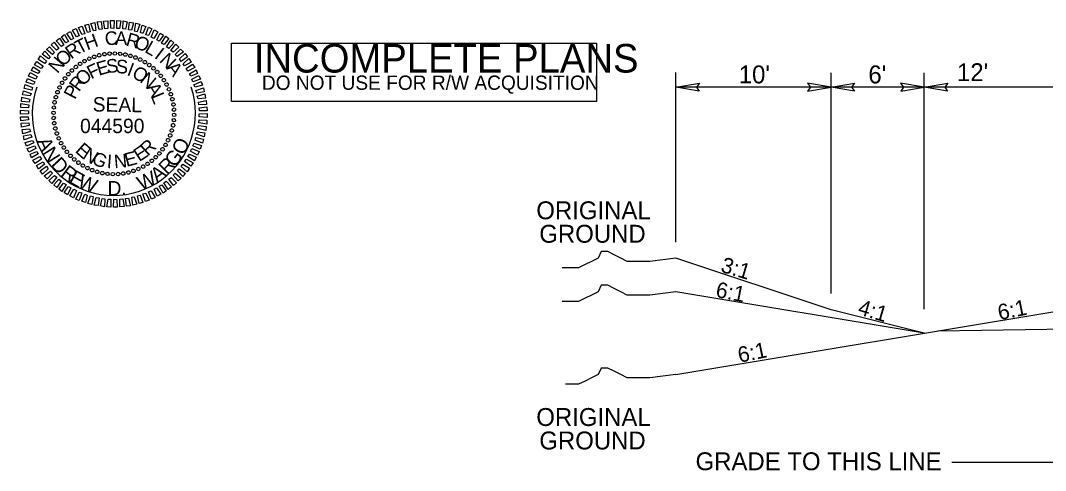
# Model space of a CAD drawing. Extents: x 2176156 to 2177167, y 76401 to 76644.
# Drawn here: x 2176901.7 to 2176967.8, y 76590.1 to 76619.1 of the extents above; entities that cross this region are included whole.
import ezdxf

# ---------------------------------------------------------------- set-up
doc = ezdxf.new("R2010")
doc.units = 0
for name, color, linetype in [('Exist Building', 7, 'Continuous'), ('Exist Roads Curbs', 7, 'Continuous'), ('Exist Roads EOP Other', 7, 'Continuous'), ('Exist Roads Soil', 7, 'Continuous'), ('Exist Structure Minor Culvert Topo', 7, 'Continuous'), ('Old_Level_1', 7, 'Continuous'), ('Old_Level_3', 7, 'Continuous'), ('PH Exist DTM Obscure Area', 7, 'Continuous'), ('Sheet Border Standard 30in CELL', 7, 'Continuous'), ('Sheet Cutting Line CELL', 7, 'Continuous')]:
    doc.layers.add(name, color=color, linetype=linetype)

msp = doc.modelspace()

# ---------------------------------------------------------------- linework, layer by layer
at = {"layer": 'Exist Building'}
msp.add_line((2176960.844, 76599.085), (2176981.96, 76599.4), dxfattribs=at)
at = {"layer": 'Exist Roads Curbs'}
for points in [[(2176943.96, 76603.771), (2176942.289, 76603.563), (2176941.871, 76603.563), (2176941.244, 76603.563), (2176940.826, 76603.563), (2176940.409, 76603.771), (2176939.991, 76603.981), (2176939.573, 76604.191), (2176939.156, 76604.191), (2176938.946, 76603.771), (2176938.528, 76603.563), (2176938.111, 76603.354), (2176937.693, 76603.146), (2176937.275, 76603.146), (2176936.858, 76603.146), (2176936.626, 76603.146)], [(2176943.959, 76601.605), (2176942.289, 76601.397), (2176941.871, 76601.397), (2176941.244, 76601.397), (2176940.826, 76601.397), (2176940.408, 76601.605), (2176939.991, 76601.814), (2176939.573, 76602.024), (2176939.155, 76602.024), (2176938.946, 76601.605), (2176938.528, 76601.397), (2176938.11, 76601.187), (2176937.693, 76600.979), (2176937.275, 76600.979), (2176936.858, 76600.979), (2176936.626, 76600.979)], [(2176943.96, 76596.271), (2176942.289, 76596.063), (2176941.871, 76596.063), (2176941.244, 76596.063), (2176940.826, 76596.063), (2176940.409, 76596.271), (2176939.991, 76596.481), (2176939.573, 76596.691), (2176939.156, 76596.691), (2176938.946, 76596.271), (2176938.528, 76596.063), (2176938.111, 76595.854), (2176937.693, 76595.646), (2176937.275, 76595.646), (2176936.858, 76595.646), (2176936.847, 76595.646)]]:
    msp.add_lwpolyline(points, dxfattribs=at)
at = {"layer": 'Exist Roads EOP Other'}
for p, q in [((2176953.96, 76600.438), (2176943.96, 76603.771)), ((2176959.96, 76598.938), (2176953.96, 76600.438))]:
    msp.add_line(p, q, dxfattribs=at)
at = {"layer": 'Exist Roads Soil'}
for p, q in [((2176959.96, 76598.938), (2176943.96, 76601.605)), ((2176943.96, 76596.271), (2176971.912, 76600.93))]:
    msp.add_line(p, q, dxfattribs=at)
at = {"layer": 'Old_Level_1'}
for points in [[(2176945.469, 76614.521), (2176943.96, 76614.781), (2176945.478, 76615.049), (2176945.285, 76614.781)], [(2176952.45, 76614.521), (2176953.96, 76614.781), (2176952.442, 76615.049), (2176952.635, 76614.781)], [(2176955.469, 76614.521), (2176953.96, 76614.781), (2176955.478, 76615.049), (2176955.285, 76614.781)], [(2176958.45, 76614.521), (2176959.96, 76614.781), (2176958.442, 76615.049), (2176958.635, 76614.781)], [(2176961.469, 76614.521), (2176959.96, 76614.781), (2176961.478, 76615.049), (2176961.285, 76614.781)]]:
    msp.add_lwpolyline(points, close=True, dxfattribs=at)
at = {"layer": 'Old_Level_3'}
for p, q in [((2176943.96, 76604.802), (2176943.96, 76615.735)), ((2176953.96, 76601.501), (2176953.96, 76615.709)), ((2176959.96, 76600.483), (2176959.96, 76615.709)), ((2176953.96, 76614.781), (2176943.96, 76614.781)), ((2176959.96, 76614.781), (2176953.96, 76614.781)), ((2176971.96, 76614.781), (2176959.96, 76614.781)), ((2176961.746, 76590.631), (2176971.314, 76590.631))]:
    msp.add_line(p, q, dxfattribs=at)
at = {"layer": 'PH Exist DTM Obscure Area'}
for p, q in [((2176905.86, 76616.472), (2176905.86, 76616.472)), ((2176906.162, 76616.627), (2176906.162, 76616.627)), ((2176906.472, 76616.751), (2176906.472, 76616.751)), ((2176906.798, 76616.844), (2176906.798, 76616.844)), ((2176907.139, 76616.906), (2176907.139, 76616.906)), ((2176907.472, 76616.953), (2176907.472, 76616.953)), ((2176907.813, 76616.96), (2176907.813, 76616.96)), ((2176908.154, 76616.937), (2176908.154, 76616.937)), ((2176908.487, 76616.883), (2176908.487, 76616.883)), ((2176908.813, 76616.813), (2176908.813, 76616.813)), ((2176909.138, 76616.705), (2176909.138, 76616.705)), ((2176909.448, 76616.565), (2176909.448, 76616.565)), ((2176905.039, 76615.868), (2176905.039, 76615.868)), ((2176905.294, 76616.1), (2176905.294, 76616.1)), ((2176905.566, 76616.294), (2176905.566, 76616.294)), ((2176909.751, 76616.41), (2176909.751, 76616.41)), ((2176910.03, 76616.216), (2176910.03, 76616.216)), ((2176910.301, 76616.007), (2176910.301, 76616.007)), ((2176910.541, 76615.775), (2176910.541, 76615.775)), ((2176904.597, 76615.356), (2176904.597, 76615.356)), ((2176904.806, 76615.627), (2176904.806, 76615.627)), ((2176910.774, 76615.519), (2176910.774, 76615.519)), ((2176910.967, 76615.248), (2176910.967, 76615.248)), ((2176904.109, 76614.465), (2176904.109, 76614.465)), ((2176904.248, 76614.775), (2176904.248, 76614.775)), ((2176904.403, 76615.077), (2176904.403, 76615.077)), ((2176911.146, 76614.953), (2176911.146, 76614.953)), ((2176911.301, 76614.651), (2176911.301, 76614.651)), ((2176903.93, 76613.814), (2176903.93, 76613.814)), ((2176904, 76614.139), (2176904, 76614.139)), ((2176911.425, 76614.341), (2176911.425, 76614.341)), ((2176911.518, 76614.015), (2176911.518, 76614.015)), ((2176903.853, 76613.14), (2176903.853, 76613.14)), ((2176903.876, 76613.481), (2176903.876, 76613.481)), ((2176911.58, 76613.674), (2176911.58, 76613.674)), ((2176911.626, 76613.341), (2176911.626, 76613.341)), ((2176903.861, 76612.799), (2176903.861, 76612.799)), ((2176903.907, 76612.465), (2176903.907, 76612.465)), ((2176911.611, 76612.659), (2176911.611, 76612.659)), ((2176911.634, 76613), (2176911.634, 76613)), ((2176903.969, 76612.124), (2176903.969, 76612.124)), ((2176904.062, 76611.799), (2176904.062, 76611.799)), ((2176911.487, 76612), (2176911.487, 76612)), ((2176911.556, 76612.326), (2176911.556, 76612.326)), ((2176904.186, 76611.489), (2176904.186, 76611.489)), ((2176904.341, 76611.187), (2176904.341, 76611.187)), ((2176911.239, 76611.365), (2176911.239, 76611.365)), ((2176911.378, 76611.675), (2176911.378, 76611.675)), ((2176904.519, 76610.892), (2176904.519, 76610.892)), ((2176904.713, 76610.621), (2176904.713, 76610.621)), ((2176910.681, 76610.512), (2176910.681, 76610.512)), ((2176910.89, 76610.784), (2176910.89, 76610.784)), ((2176911.084, 76611.063), (2176911.084, 76611.063)), ((2176904.946, 76610.365), (2176904.946, 76610.365)), ((2176905.186, 76610.133), (2176905.186, 76610.133)), ((2176905.457, 76609.923), (2176905.457, 76609.923)), ((2176909.921, 76609.846), (2176909.921, 76609.846)), ((2176910.192, 76610.04), (2176910.192, 76610.04)), ((2176910.448, 76610.272), (2176910.448, 76610.272)), ((2176905.736, 76609.73), (2176905.736, 76609.73)), ((2176906.038, 76609.575), (2176906.038, 76609.575)), ((2176906.348, 76609.435), (2176906.348, 76609.435)), ((2176906.674, 76609.327), (2176906.674, 76609.327)), ((2176906.999, 76609.257), (2176906.999, 76609.257)), ((2176907.333, 76609.203), (2176907.333, 76609.203)), ((2176907.674, 76609.179), (2176907.674, 76609.179)), ((2176908.015, 76609.187), (2176908.015, 76609.187)), ((2176908.348, 76609.234), (2176908.348, 76609.234)), ((2176908.689, 76609.296), (2176908.689, 76609.296)), ((2176909.014, 76609.389), (2176909.014, 76609.389)), ((2176909.324, 76609.513), (2176909.324, 76609.513)), ((2176909.627, 76609.668), (2176909.627, 76609.668))]:
    msp.add_line(p, q, dxfattribs=at)
for points in [[(2176907.17, 76618.541), (2176907.085, 76619.037), (2176907.348, 76619.068), (2176907.356, 76618.565)], [(2176907.557, 76618.58), (2176907.519, 76619.084), (2176907.774, 76619.076), (2176907.743, 76618.572)], [(2176907.929, 76618.572), (2176907.929, 76619.076), (2176908.185, 76619.068), (2176908.115, 76618.565)], [(2176905.333, 76618.022), (2176905.085, 76618.456), (2176905.325, 76618.565), (2176905.504, 76618.092)], [(2176905.674, 76618.185), (2176905.473, 76618.634), (2176905.705, 76618.727), (2176905.868, 76618.231)], [(2176906.054, 76618.309), (2176905.876, 76618.774), (2176906.116, 76618.844), (2176906.217, 76618.363)], [(2176906.426, 76618.41), (2176906.263, 76618.898), (2176906.527, 76618.952), (2176906.589, 76618.448)], [(2176906.798, 76618.495), (2176906.674, 76618.991), (2176906.93, 76619.014), (2176906.984, 76618.518)], [(2176908.317, 76618.549), (2176908.348, 76619.053), (2176908.604, 76619.006), (2176908.503, 76618.518)], [(2176908.689, 76618.487), (2176908.759, 76618.983), (2176909.014, 76618.944), (2176908.875, 76618.464)], [(2176909.084, 76618.402), (2176909.162, 76618.906), (2176909.425, 76618.844), (2176909.247, 76618.363)], [(2176909.456, 76618.301), (2176909.572, 76618.782), (2176909.813, 76618.704), (2176909.619, 76618.247)], [(2176909.805, 76618.162), (2176909.983, 76618.65), (2176910.2, 76618.557), (2176909.983, 76618.107)], [(2176910.154, 76618.014), (2176910.347, 76618.472), (2176910.588, 76618.363), (2176910.324, 76617.929)], [(2176904.364, 76617.41), (2176904.031, 76617.782), (2176904.24, 76617.945), (2176904.512, 76617.511)], [(2176904.659, 76617.642), (2176904.372, 76618.038), (2176904.574, 76618.185), (2176904.829, 76617.735)], [(2176905, 76617.836), (2176904.713, 76618.255), (2176904.953, 76618.379), (2176905.147, 76617.929)], [(2176910.51, 76617.836), (2176910.719, 76618.278), (2176910.952, 76618.146), (2176910.657, 76617.743)], [(2176910.812, 76617.627), (2176911.084, 76618.076), (2176911.285, 76617.914), (2176910.983, 76617.534)], [(2176911.13, 76617.394), (2176911.417, 76617.821), (2176911.618, 76617.65), (2176911.277, 76617.286)], [(2176903.527, 76616.604), (2176903.124, 76616.906), (2176903.295, 76617.108), (2176903.636, 76616.743)], [(2176903.799, 76616.898), (2176903.403, 76617.216), (2176903.597, 76617.394), (2176903.923, 76617.022)], [(2176904.054, 76617.17), (2176903.713, 76617.511), (2176903.899, 76617.697), (2176904.202, 76617.278)], [(2176911.425, 76617.154), (2176911.742, 76617.557), (2176911.928, 76617.371), (2176911.572, 76617.038)], [(2176911.704, 76616.883), (2176912.037, 76617.247), (2176912.223, 76617.061), (2176911.82, 76616.759)], [(2176903.062, 76615.999), (2176902.628, 76616.232), (2176902.783, 76616.449), (2176903.186, 76616.139)], [(2176903.295, 76616.309), (2176902.876, 76616.573), (2176903.024, 76616.798), (2176903.396, 76616.457)], [(2176911.975, 76616.604), (2176912.331, 76616.953), (2176912.494, 76616.743), (2176912.083, 76616.449)], [(2176912.207, 76616.302), (2176912.587, 76616.627), (2176912.734, 76616.402), (2176912.3, 76616.154)], [(2176902.876, 76615.666), (2176902.435, 76615.86), (2176902.551, 76616.1), (2176902.969, 76615.813)], [(2176912.409, 76615.984), (2176912.82, 76616.278), (2176912.967, 76616.046), (2176912.517, 76615.829)], [(2176912.61, 76615.643), (2176913.044, 76615.914), (2176913.145, 76615.674), (2176912.703, 76615.496)], [(2176902.566, 76614.969), (2176902.086, 76615.108), (2176902.187, 76615.348), (2176902.652, 76615.131)], [(2176902.721, 76615.31), (2176902.241, 76615.488), (2176902.357, 76615.728), (2176902.799, 76615.48)], [(2176912.765, 76615.31), (2176913.223, 76615.542), (2176913.323, 76615.294), (2176912.843, 76615.139)], [(2176912.905, 76614.945), (2176913.378, 76615.147), (2176913.463, 76614.907), (2176912.982, 76614.783)], [(2176902.349, 76614.225), (2176901.869, 76614.287), (2176901.923, 76614.55), (2176902.411, 76614.387)], [(2176902.45, 76614.597), (2176901.97, 76614.697), (2176902.024, 76614.953), (2176902.512, 76614.759)], [(2176913.029, 76614.573), (2176913.525, 76614.752), (2176913.571, 76614.496), (2176913.083, 76614.411)], [(2176902.287, 76613.829), (2176901.791, 76613.876), (2176901.822, 76614.139), (2176902.326, 76614.015)], [(2176913.122, 76614.201), (2176913.61, 76614.349), (2176913.657, 76614.085), (2176913.168, 76614.039)], [(2176913.192, 76613.829), (2176913.695, 76613.938), (2176913.719, 76613.674), (2176913.223, 76613.643)], [(2176902.241, 76613.07), (2176901.737, 76613.047), (2176901.737, 76613.31), (2176902.241, 76613.256)], [(2176902.249, 76613.457), (2176901.745, 76613.473), (2176901.76, 76613.729), (2176902.264, 76613.643)], [(2176913.238, 76613.457), (2176913.742, 76613.519), (2176913.757, 76613.256), (2176913.254, 76613.271)], [(2176902.249, 76612.682), (2176901.745, 76612.62), (2176901.729, 76612.884), (2176902.233, 76612.868)], [(2176902.295, 76612.31), (2176901.791, 76612.202), (2176901.768, 76612.465), (2176902.264, 76612.496)], [(2176913.238, 76612.682), (2176913.742, 76612.667), (2176913.726, 76612.411), (2176913.223, 76612.496)], [(2176913.246, 76613.07), (2176913.75, 76613.093), (2176913.75, 76612.83), (2176913.246, 76612.884)], [(2176902.365, 76611.938), (2176901.877, 76611.791), (2176901.83, 76612.055), (2176902.318, 76612.101)], [(2176913.137, 76611.915), (2176913.618, 76611.853), (2176913.564, 76611.59), (2176913.075, 76611.752)], [(2176913.199, 76612.31), (2176913.695, 76612.264), (2176913.664, 76612), (2176913.161, 76612.124)], [(2176902.458, 76611.566), (2176901.962, 76611.388), (2176901.915, 76611.644), (2176902.404, 76611.729)], [(2176902.582, 76611.194), (2176902.109, 76610.993), (2176902.024, 76611.233), (2176902.504, 76611.357)], [(2176912.92, 76611.171), (2176913.401, 76611.032), (2176913.3, 76610.791), (2176912.835, 76611.008)], [(2176913.037, 76611.543), (2176913.517, 76611.442), (2176913.463, 76611.187), (2176912.975, 76611.38)], [(2176902.721, 76610.83), (2176902.264, 76610.598), (2176902.163, 76610.846), (2176902.644, 76611.001)], [(2176902.876, 76610.497), (2176902.442, 76610.226), (2176902.342, 76610.466), (2176902.783, 76610.644)], [(2176912.61, 76610.474), (2176913.052, 76610.28), (2176912.936, 76610.04), (2176912.517, 76610.326)], [(2176912.765, 76610.83), (2176913.246, 76610.652), (2176913.13, 76610.412), (2176912.688, 76610.66)], [(2176903.078, 76610.156), (2176902.667, 76609.861), (2176902.52, 76610.094), (2176902.969, 76610.311)], [(2176903.279, 76609.838), (2176902.9, 76609.513), (2176902.752, 76609.737), (2176903.186, 76609.985)], [(2176912.192, 76609.83), (2176912.61, 76609.567), (2176912.463, 76609.342), (2176912.091, 76609.683)], [(2176912.424, 76610.14), (2176912.858, 76609.908), (2176912.703, 76609.691), (2176912.3, 76610.001)], [(2176903.512, 76609.536), (2176903.155, 76609.187), (2176902.993, 76609.396), (2176903.403, 76609.691)], [(2176903.783, 76609.257), (2176903.45, 76608.893), (2176903.264, 76609.079), (2176903.667, 76609.381)], [(2176911.688, 76609.241), (2176912.083, 76608.924), (2176911.89, 76608.745), (2176911.564, 76609.117)], [(2176911.959, 76609.536), (2176912.362, 76609.234), (2176912.192, 76609.032), (2176911.851, 76609.396)], [(2176904.062, 76608.986), (2176903.744, 76608.583), (2176903.558, 76608.769), (2176903.915, 76609.102)], [(2176904.357, 76608.745), (2176904.07, 76608.319), (2176903.868, 76608.49), (2176904.209, 76608.854)], [(2176904.674, 76608.513), (2176904.403, 76608.063), (2176904.202, 76608.226), (2176904.504, 76608.606)], [(2176910.828, 76608.497), (2176911.115, 76608.102), (2176910.913, 76607.955), (2176910.657, 76608.404)], [(2176911.122, 76608.73), (2176911.456, 76608.358), (2176911.246, 76608.195), (2176910.975, 76608.629)], [(2176911.432, 76608.97), (2176911.773, 76608.629), (2176911.587, 76608.443), (2176911.285, 76608.862)], [(2176904.977, 76608.304), (2176904.767, 76607.862), (2176904.535, 76607.994), (2176904.829, 76608.397)], [(2176905.333, 76608.125), (2176905.139, 76607.668), (2176904.899, 76607.777), (2176905.163, 76608.211)], [(2176905.682, 76607.978), (2176905.504, 76607.49), (2176905.287, 76607.583), (2176905.504, 76608.032)], [(2176906.031, 76607.839), (2176905.914, 76607.358), (2176905.674, 76607.436), (2176905.868, 76607.893)], [(2176909.433, 76607.831), (2176909.611, 76607.366), (2176909.371, 76607.296), (2176909.27, 76607.777)], [(2176909.813, 76607.955), (2176910.014, 76607.505), (2176909.782, 76607.412), (2176909.619, 76607.908)], [(2176910.154, 76608.118), (2176910.402, 76607.684), (2176910.161, 76607.575), (2176909.983, 76608.048)], [(2176910.487, 76608.304), (2176910.774, 76607.885), (2176910.533, 76607.761), (2176910.34, 76608.211)], [(2176906.403, 76607.738), (2176906.325, 76607.234), (2176906.062, 76607.296), (2176906.24, 76607.777)], [(2176906.798, 76607.653), (2176906.728, 76607.157), (2176906.472, 76607.195), (2176906.612, 76607.676)], [(2176907.17, 76607.591), (2176907.139, 76607.087), (2176906.883, 76607.133), (2176906.984, 76607.622)], [(2176907.557, 76607.567), (2176907.557, 76607.064), (2176907.302, 76607.071), (2176907.371, 76607.575)], [(2176907.929, 76607.56), (2176907.968, 76607.056), (2176907.712, 76607.064), (2176907.743, 76607.567)], [(2176908.317, 76607.598), (2176908.402, 76607.102), (2176908.139, 76607.071), (2176908.131, 76607.575)], [(2176908.689, 76607.645), (2176908.813, 76607.149), (2176908.557, 76607.126), (2176908.503, 76607.622)], [(2176909.061, 76607.73), (2176909.224, 76607.242), (2176908.96, 76607.188), (2176908.898, 76607.691)]]:
    msp.add_lwpolyline(points, close=True, dxfattribs=at)
for centre, major_axis in [((2176905.57, 76616.293), (-0.0624, 0.0925)), ((2176905.859, 76616.47), (-0.0541, 0.0976)), ((2176906.162, 76616.621), (-0.045, 0.102)), ((2176906.478, 76616.745), (-0.036, 0.106)), ((2176906.803, 76616.842), (-0.027, 0.108)), ((2176907.135, 76616.909), (-0.017, 0.11)), ((2176907.472, 76616.948), (-0.008, 0.111)), ((2176907.811, 76616.957), (0.002, 0.112)), ((2176908.15, 76616.936), (0.012, 0.111)), ((2176908.485, 76616.886), (0.021, 0.11)), ((2176908.815, 76616.807), (0.031, 0.107)), ((2176909.137, 76616.699), (0.04, 0.104)), ((2176909.448, 76616.564), (0.049, 0.1)), ((2176909.746, 76616.402), (0.0575, 0.0957)), ((2176905.043, 76615.866), (-0.0775, 0.0803)), ((2176905.297, 76616.091), (-0.0702, 0.0867)), ((2176910.028, 76616.215), (0.0656, 0.0903)), ((2176910.294, 76616.004), (0.0732, 0.0842)), ((2176910.54, 76615.77), (0.0803, 0.0775)), ((2176904.411, 76615.072), (-0.0957, 0.0575)), ((2176904.598, 76615.355), (-0.0903, 0.0656)), ((2176904.81, 76615.62), (-0.0842, 0.0732)), ((2176910.765, 76615.516), (0.0867, 0.0702)), ((2176910.966, 76615.244), (0.0925, 0.0624)), ((2176904.114, 76614.463), (-0.104, 0.04)), ((2176904.249, 76614.774), (-0.1, 0.049)), ((2176911.143, 76614.954), (0.0976, 0.0541)), ((2176911.295, 76614.651), (0.102, 0.045)), ((2176911.419, 76614.335), (0.106, 0.036)), ((2176903.927, 76613.812), (-0.11, 0.021)), ((2176904.007, 76614.141), (-0.107, 0.031)), ((2176911.515, 76614.01), (0.108, 0.027)), ((2176911.583, 76613.678), (0.11, 0.017)), ((2176903.857, 76613.138), (-0.112, 0.002)), ((2176903.877, 76613.476), (-0.111, 0.012)), ((2176911.621, 76613.341), (0.111, 0.008)), ((2176911.63, 76613.002), (0.112, -0.002)), ((2176903.866, 76612.799), (-0.111, -0.008)), ((2176903.904, 76612.462), (-0.11, -0.017)), ((2176911.61, 76612.663), (0.111, -0.012)), ((2176903.972, 76612.129), (-0.108, -0.027)), ((2176904.068, 76611.804), (-0.106, -0.036)), ((2176911.373, 76611.677), (0.104, -0.04)), ((2176911.48, 76611.998), (0.107, -0.031)), ((2176911.559, 76612.328), (0.11, -0.021)), ((2176904.192, 76611.489), (-0.102, -0.045)), ((2176904.343, 76611.185), (-0.0976, -0.0541)), ((2176911.076, 76611.068), (0.0957, -0.0575)), ((2176911.237, 76611.366), (0.1, -0.049)), ((2176904.521, 76610.896), (-0.0925, -0.0624)), ((2176904.722, 76610.623), (-0.0867, -0.0702)), ((2176904.947, 76610.369), (-0.0803, -0.0775)), ((2176910.677, 76610.519), (0.0842, -0.0732)), ((2176910.888, 76610.785), (0.0903, -0.0656)), ((2176905.193, 76610.136), (-0.0732, -0.0842)), ((2176905.459, 76609.925), (-0.0656, -0.0903)), ((2176905.741, 76609.738), (-0.0575, -0.0957)), ((2176909.917, 76609.847), (0.0624, -0.0925)), ((2176910.19, 76610.049), (0.0702, -0.0867)), ((2176910.444, 76610.273), (0.0775, -0.0803)), ((2176906.039, 76609.576), (-0.049, -0.1)), ((2176906.35, 76609.441), (-0.04, -0.104)), ((2176906.672, 76609.333), (-0.031, -0.107)), ((2176907.002, 76609.254), (-0.021, -0.11)), ((2176907.337, 76609.204), (-0.012, -0.111)), ((2176907.676, 76609.183), (-0.002, -0.112)), ((2176908.015, 76609.192), (0.008, -0.111)), ((2176908.352, 76609.23), (0.017, -0.11)), ((2176908.684, 76609.298), (0.027, -0.108)), ((2176909.009, 76609.394), (0.036, -0.106)), ((2176909.325, 76609.518), (0.045, -0.102)), ((2176909.628, 76609.67), (0.0541, -0.0976))]:
    msp.add_ellipse(centre, major_axis=major_axis, ratio=0.999708, dxfattribs=at)
at = {"layer": 'Sheet Border Standard 30in CELL'}
msp.add_lwpolyline([(2176915.33, 76613.857), (2176915.33, 76617.617), (2176938.85, 76617.617), (2176938.85, 76613.857)], close=True, dxfattribs=at)
at = {"layer": 'Sheet Cutting Line CELL'}
msp.add_ellipse((2176907.743, 76613.07), major_axis=(3.494, 3.955), ratio=0.993455, start_param=1.958957, end_param=5.764947, dxfattribs=at)

# ---------------------------------------------------------------- texts
at = {"layer": 'Exist Roads Curbs'}
for s, rotation, p in [('3:1', 343.53506, (2176946.795, 76602.904)), ('6:1', 349.18318, (2176946.476, 76601.276)), ('4:1', 343.53506, (2176955.627, 76600.171)), ('6:1', 11.48655, (2176964.812, 76599.768)), ('6:1', 11.48655, (2176948.062, 76597.027))]:
    msp.add_text(s, height=1.0064, rotation=rotation, dxfattribs=at).set_placement(p)
at = {"layer": 'Exist Structure Minor Culvert Topo'}
for s, height, p in [("10'", 1.1533, (2176948.012, 76615.033)), ("6'", 1.1533, (2176956.366, 76615.033)), ("12' ", 1.1533, (2176962.075, 76615.176)), ('ORIGINAL', 1.1533, (2176934.967, 76606.278)), ('GROUND', 1.1533, (2176935.161, 76604.766)), ('ORIGINAL', 1.1533, (2176934.967, 76592.96)), ('GROUND', 1.1533, (2176935.161, 76591.448)), ('GRADE TO THIS LINE', 1.15334, (2176945.229, 76590.108))]:
    msp.add_text(s, height=height, dxfattribs=at).set_placement(p)
at = {"layer": 'PH Exist DTM Obscure Area'}
for s, height, rotation, p in [('C', 0.874, 6.21987, (2176907.209, 76617.464)), ('T', 0.874, 27.81977, (2176905.527, 76616.898)), ('H', 0.874, 20.61948, (2176906.031, 76617.154)), ('A', 0.874, 359.02032, (2176907.821, 76617.511)), ('R', 0.874, 344.6211, (2176908.472, 76617.48)), ('O', 0.874, 337.42116, (2176908.991, 76617.363)), ('L', 0.874, 330.22088, (2176909.673, 76617.077)), ('O', 0.874, 42.22174, (2176904.465, 76616.077)), ('R', 0.874, 35.02051, (2176905, 76616.557)), ('I', 0.874, 323.02014, (2176910.301, 76616.705)), ('N', 0.874, 49.4235, (2176904.109, 76615.627)), ('E', 0.874, 16.61107, (2176906.775, 76615.519)), ('S', 0.874, 7.25561, (2176907.309, 76615.682)), ('S', 0.874, 357.9004, (2176907.867, 76615.689)), ('N', 0.874, 315.81891, (2176910.634, 76616.464)), ('O', 0.874, 44.68124, (2176905.767, 76614.829)), ('F', 0.874, 25.96703, (2176906.279, 76615.286)), ('I', 0.874, 339.1896, (2176908.534, 76615.581)), ('O', 0.874, 329.83348, (2176908.844, 76615.472)), ('N', 0.874, 320.47661, (2176909.363, 76615.162)), ('A', 0.874, 308.61715, (2176911.091, 76616.007)), ('R', 0.874, 54.03965, (2176905.496, 76614.449)), ('P', 0.874, 63.39889, (2176905.248, 76613.953)), ('A', 0.874, 301.76027, (2176909.805, 76614.759)), ('L', 0.874, 292.40085, (2176910.107, 76614.225)), ('SEAL', 0.9297, 359, (2176906.372, 76613.225)), ('A', 0.93, 293.55151, (2176902.76, 76611.309)), ('E', 0.874, 318.27689, (2176905.201, 76610.644)), ('R', 0.874, 42.48141, (2176909.929, 76610.319)), ('O', 0.93, 63.16721, (2176912.25, 76610.358)), ('N', 0.93, 302.39494, (2176903.083, 76610.568)), ('N', 0.874, 327.63396, (2176905.666, 76610.226)), ('G', 0.874, 336.99024, (2176906.255, 76609.877)), ('N', 0.874, 5.05639, (2176907.79, 76609.559)), ('E', 0.874, 14.41176, (2176908.557, 76609.652)), ('E', 0.874, 33.12409, (2176909.379, 76609.954)), ('G', 0.93, 52.61508, (2176911.668, 76609.57)), ('D', 0.93, 313.1429, (2176903.622, 76609.75)), ('I', 0.874, 355.7012, (2176907.271, 76609.582)), ('R', 0.93, 45.25998, (2176911.181, 76609.09)), ('R', 0.93, 323.04588, (2176904.244, 76609.098)), ('E', 0.93, 330.54386, (2176904.786, 76608.681)), ('W', 0.93, 337.66293, (2176905.347, 76608.353)), ('W', 0.93, 24.216, (2176909.505, 76608.107)), ('A', 0.93, 36.56448, (2176910.533, 76608.609)), ('D', 0.93, 0.34358, (2176907.338, 76607.805)), ('.', 0.93, 10.14458, (2176908.24, 76607.818))]:
    msp.add_text(s, height=height, rotation=rotation, dxfattribs=at).set_placement(p)
msp.add_text('044590 ', height=0.9297, dxfattribs=at).set_placement((2176905.567, 76611.828))
at = {"layer": 'Sheet Border Standard 30in CELL'}
for s, height, p in [('INCOMPLETE PLANS', 1.8432, (2176916.762, 76615.729)), ('DO NOT USE FOR R/W ACQUISITION', 0.9216, (2176917.282, 76614.617))]:
    msp.add_text(s, height=height, dxfattribs=at).set_placement(p)

doc.saveas('drawing.dxf')
